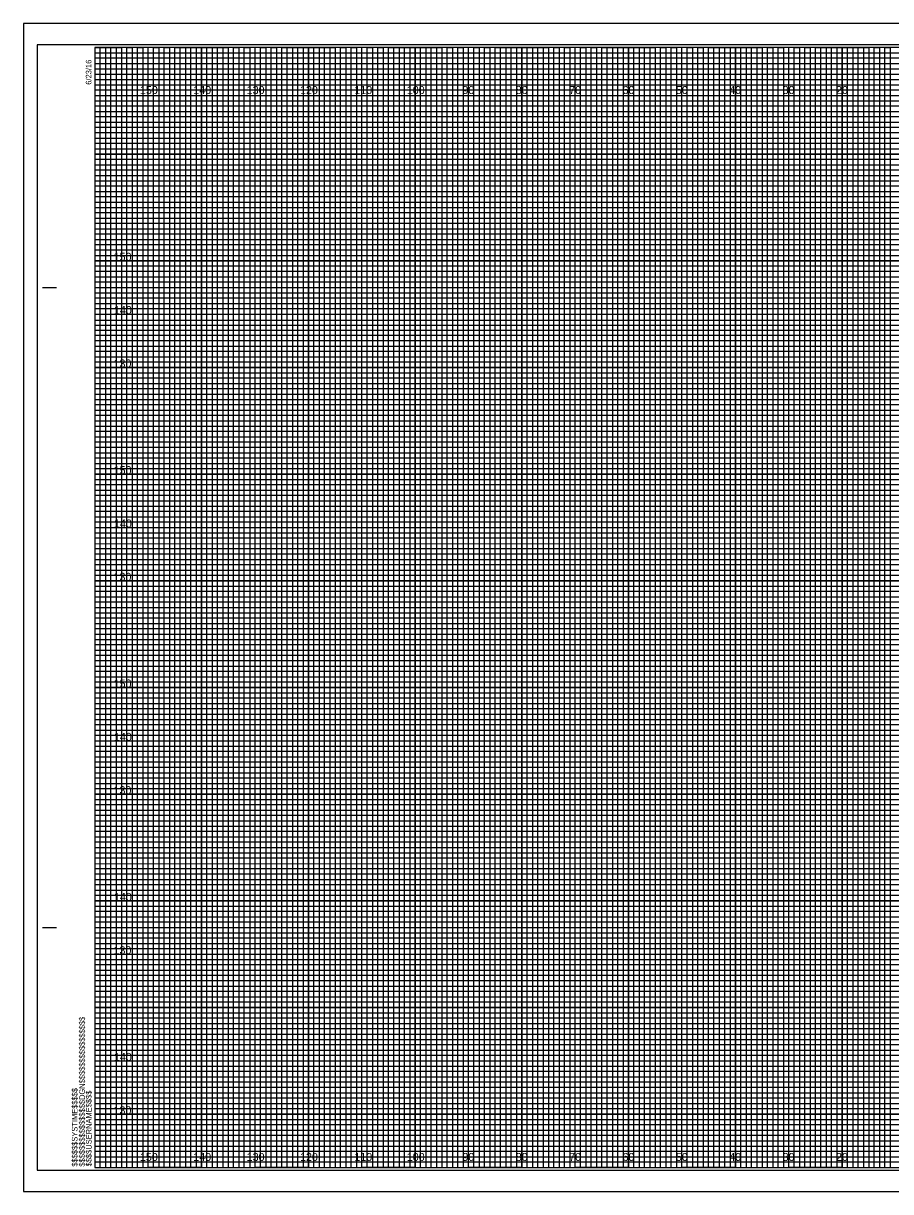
# Model space of a CAD drawing. Extents: x -13 to 323, y -5 to 2634.
# Drawn here: x -13.4 to 149.1, y -4.5 to 214.5 of the extents above; entities that cross this region are included whole.
import ezdxf

# ---------------------------------------------------------------- set-up
doc = ezdxf.new("R2010")
doc.units = 0
for name, color, linetype in [('Exist Cross Section Cell', 7, 'Continuous'), ('Exist XS Center Line Elevation Label', 7, 'Continuous'), ('Exist XS Ground Line', 7, 'Continuous'), ('Prop CMT Pvmt Surface Shoulder', 7, 'Continuous'), ('Prop CMT Pvmt Wedge Surface 3', 7, 'Continuous'), ('Prop CMT Shld Paved Course 1', 7, 'Continuous'), ('Prop CMT Shld Paved Course 2', 7, 'Continuous'), ('Prop CMT Shld Paved Course 3', 7, 'Continuous'), ('Prop CMT Slope Grass', 7, 'Continuous'), ('Prop CMT Subgrade Earthwork', 7, 'Continuous'), ('Scratch_Level_0', 7, 'Continuous')]:
    doc.layers.add(name, color=color, linetype=linetype)

msp = doc.modelspace()

# ---------------------------------------------------------------- linework, layer by layer
at = {"layer": 'Exist XS Center Line Elevation Label'}
for points in [[(0, 210), (5, 210), (5, 0), (15, 0), (15, 210), (25, 210), (25, 0), (35, 0), (35, 210), (45, 210), (45, 0), (55, 0), (55, 210), (65, 210), (65, 0), (75, 0), (75, 210), (85, 210), (85, 0), (95, 0), (95, 210), (105, 210), (105, 0), (115, 0), (115, 210), (125, 210), (125, 0), (135, 0), (135, 210), (145, 210), (145, 0), (155, 0)], [(0, 205), (275, 205)], [(0, 185), (320, 185), (320, 195), (0, 195)], [(0, 165), (320, 165), (320, 175), (0, 175)], [(0, 145), (320, 145), (320, 155), (0, 155)], [(0, 125), (320, 125), (320, 135), (0, 135)], [(0, 105), (320, 105), (320, 115), (0, 115)], [(0, 85), (320, 85), (320, 95), (0, 95)], [(0, 65), (320, 65), (320, 75), (0, 75)], [(0, 45), (320, 45), (320, 55), (0, 55)], [(0, 25), (320, 25), (320, 35), (0, 35)], [(0, 5), (320, 5), (320, 15), (0, 15)]]:
    msp.add_lwpolyline(points, dxfattribs=at)
at = {"layer": 'Exist XS Ground Line'}
for p, q in [((10, 210), (0, 210)), ((10, 0), (10, 210)), ((30, 210), (20, 210)), ((20, 210), (20, 0)), ((30, 0), (30, 210)), ((50, 210), (40, 210)), ((40, 210), (40, 0)), ((50, 0), (50, 210)), ((70, 210), (60, 210)), ((60, 210), (60, 0)), ((70, 0), (70, 210)), ((90, 210), (80, 210)), ((80, 210), (80, 0)), ((90, 0), (90, 210)), ((110, 210), (100, 210)), ((100, 210), (100, 0)), ((110, 0), (110, 210)), ((130, 210), (120, 210)), ((120, 210), (120, 0)), ((130, 0), (130, 210)), ((150, 210), (140, 210)), ((140, 210), (140, 0)), ((20, 0), (10, 0)), ((40, 0), (30, 0)), ((60, 0), (50, 0)), ((80, 0), (70, 0)), ((100, 0), (90, 0)), ((120, 0), (110, 0)), ((140, 0), (130, 0))]:
    msp.add_line(p, q, dxfattribs=at)
for points in [[(0, 200), (320, 200), (320, 190), (0, 190)], [(0, 180), (320, 180), (320, 170), (0, 170)], [(0, 160), (320, 160), (320, 150), (0, 150)], [(0, 140), (320, 140), (320, 130), (0, 130)], [(0, 120), (320, 120), (320, 110), (0, 110)], [(0, 100), (320, 100), (320, 90), (0, 90)], [(0, 80), (320, 80), (320, 70), (0, 70)], [(0, 60), (320, 60), (320, 50), (0, 50)], [(0, 40), (320, 40), (320, 30), (0, 30)], [(0, 20), (320, 20), (320, 10), (0, 10)]]:
    msp.add_lwpolyline(points, dxfattribs=at)
at = {"layer": 'Prop CMT Pvmt Surface Shoulder'}
for points in [[(0, 0), (1, 0), (1, 210), (2, 210), (2, 0)], [(2, 0), (3, 0), (3, 210), (4, 210), (4, 0)], [(5, 0), (6, 0), (6, 210), (7, 210), (7, 0)], [(7, 0), (8, 0), (8, 210), (9, 210), (9, 0)], [(10, 0), (11, 0), (11, 210), (12, 210), (12, 0)], [(12, 0), (13, 0), (13, 210), (14, 210), (14, 0)], [(15, 0), (16, 0), (16, 210), (17, 210), (17, 0)], [(17, 0), (18, 0), (18, 210), (19, 210), (19, 0)], [(20, 0), (21, 0), (21, 210), (22, 210), (22, 0)], [(22, 0), (23, 0), (23, 210), (24, 210), (24, 0)], [(25, 0), (26, 0), (26, 210), (27, 210), (27, 0)], [(27, 0), (28, 0), (28, 210), (29, 210), (29, 0)], [(30, 0), (31, 0), (31, 210), (32, 210), (32, 0)], [(32, 0), (33, 0), (33, 210), (34, 210), (34, 0)], [(35, 0), (36, 0), (36, 210), (37, 210), (37, 0)], [(37, 0), (38, 0), (38, 210), (39, 210), (39, 0)], [(40, 0), (41, 0), (41, 210), (42, 210), (42, 0)], [(42, 0), (43, 0), (43, 210), (44, 210), (44, 0)], [(45, 0), (46, 0), (46, 210), (47, 210), (47, 0)], [(47, 0), (48, 0), (48, 210), (49, 210), (49, 0)], [(50, 0), (51, 0), (51, 210), (52, 210), (52, 0)], [(52, 0), (53, 0), (53, 210), (54, 210), (54, 0)], [(55, 0), (56, 0), (56, 210), (57, 210), (57, 0)], [(57, 0), (58, 0), (58, 210), (59, 210), (59, 0)], [(60, 0), (61, 0), (61, 210), (62, 210), (62, 0)], [(62, 0), (63, 0), (63, 210), (64, 210), (64, 0)], [(65, 0), (66, 0), (66, 210), (67, 210), (67, 0)], [(67, 0), (68, 0), (68, 210), (69, 210), (69, 0)], [(70, 0), (71, 0), (71, 210), (72, 210), (72, 0)], [(72, 0), (73, 0), (73, 210), (74, 210), (74, 0)], [(75, 0), (76, 0), (76, 210), (77, 210), (77, 0)], [(77, 0), (78, 0), (78, 210), (79, 210), (79, 0)], [(80, 0), (81, 0), (81, 210), (82, 210), (82, 0)], [(82, 0), (83, 0), (83, 210), (84, 210), (84, 0)], [(85, 0), (86, 0), (86, 210), (87, 210), (87, 0)], [(87, 0), (88, 0), (88, 210), (89, 210), (89, 0)], [(90, 0), (91, 0), (91, 210), (92, 210), (92, 0)], [(92, 0), (93, 0), (93, 210), (94, 210), (94, 0)], [(95, 0), (96, 0), (96, 210), (97, 210), (97, 0)], [(97, 0), (98, 0), (98, 210), (99, 210), (99, 0)], [(100, 0), (101, 0), (101, 210), (102, 210), (102, 0)], [(102, 0), (103, 0), (103, 210), (104, 210), (104, 0)], [(105, 0), (106, 0), (106, 210), (107, 210), (107, 0)], [(107, 0), (108, 0), (108, 210), (109, 210), (109, 0)], [(110, 0), (111, 0), (111, 210), (112, 210), (112, 0)], [(112, 0), (113, 0), (113, 210), (114, 210), (114, 0)], [(115, 0), (116, 0), (116, 210), (117, 210), (117, 0)], [(117, 0), (118, 0), (118, 210), (119, 210), (119, 0)], [(120, 0), (121, 0), (121, 210), (122, 210), (122, 0)], [(122, 0), (123, 0), (123, 210), (124, 210), (124, 0)], [(125, 0), (126, 0), (126, 210), (127, 210), (127, 0)], [(127, 0), (128, 0), (128, 210), (129, 210), (129, 0)], [(130, 0), (131, 0), (131, 210), (132, 210), (132, 0)], [(132, 0), (133, 0), (133, 210), (134, 210), (134, 0)], [(135, 0), (136, 0), (136, 210), (137, 210), (137, 0)], [(137, 0), (138, 0), (138, 210), (139, 210), (139, 0)], [(140, 0), (141, 0), (141, 210), (142, 210), (142, 0)], [(142, 0), (143, 0), (143, 210), (144, 210), (144, 0)], [(145, 0), (146, 0), (146, 210), (147, 210), (147, 0)], [(147, 0), (148, 0), (148, 210), (149, 210), (149, 0)]]:
    msp.add_lwpolyline(points, dxfattribs=at)
at = {"layer": 'Prop CMT Pvmt Wedge Surface 3'}
for p, q in [((-9.8, 165), (-7.3, 165)), ((-9.7, 165), (-7.2, 165)), ((-9.8, 45), (-7.3, 45)), ((-9.7, 45), (-7.2, 45)), ((0, 0), (0, 0)), ((0, 0), (0, 0)), ((0, 0), (0, 0)), ((0, 0), (0, 0)), ((0, 0), (0, 0)), ((0, 0), (0, 0)), ((0, 0), (0, 0))]:
    msp.add_line(p, q, dxfattribs=at)
msp.add_lwpolyline([(320, 210), (0, 210), (0, 0), (320, 0)], close=True, dxfattribs=at)
at = {"layer": 'Prop CMT Shld Paved Course 1'}
for p, q in [((10, 0), (10, 210)), ((20, 0), (20, 210)), ((30, 0), (30, 210)), ((40, 0), (40, 210)), ((50, 0), (50, 210)), ((60, 0), (60, 210)), ((70, 0), (70, 210)), ((80, 0), (80, 210)), ((90, 0), (90, 210)), ((100, 0), (100, 210)), ((110, 0), (110, 210)), ((120, 0), (120, 210)), ((130, 0), (130, 210)), ((140, 0), (140, 210)), ((0, 200), (320, 200)), ((0, 190), (320, 190)), ((0, 180), (320, 180)), ((0, 170), (320, 170)), ((0, 160), (320, 160)), ((0, 150), (320, 150)), ((0, 140), (320, 140)), ((0, 130), (320, 130)), ((0, 120), (320, 120)), ((0, 110), (320, 110)), ((0, 100), (320, 100)), ((0, 90), (320, 90)), ((0, 80), (320, 80)), ((0, 70), (320, 70)), ((0, 60), (320, 60)), ((0, 50), (320, 50)), ((0, 40), (320, 40)), ((0, 30), (320, 30)), ((0, 20), (320, 20)), ((0, 10), (320, 10))]:
    msp.add_line(p, q, dxfattribs=at)
at = {"layer": 'Prop CMT Shld Paved Course 2'}
for p, q in [((323.3, 214.5), (-13.4, 214.5)), ((-13.4, 214.5), (-13.4, -4.5)), ((-13.4, -4.5), (323.3, -4.5))]:
    msp.add_line(p, q, dxfattribs=at)
at = {"layer": 'Prop CMT Slope Grass'}
msp.add_lwpolyline([(-10.8, -0.5), (322.4, -0.5), (322.4, 210.5), (-10.8, 210.5)], close=True, dxfattribs=at)
at = {"layer": 'Prop CMT Subgrade Earthwork'}
msp.add_lwpolyline([(-13.4, -4.5), (323.3, -4.5), (323.3, 214.5), (-13.4, 214.5)], close=True, dxfattribs=at)
at = {"layer": 'Scratch_Level_0'}
for p, q in [((0, 209), (260, 209)), ((260, 207.98), (0, 207.98)), ((0, 207.98), (0, 207)), ((0, 207), (260, 207)), ((260, 205.89), (0, 205.89)), ((0, 205.89), (0, 204)), ((0, 204), (320, 204))]:
    msp.add_line(p, q, dxfattribs=at)
for points in [[(0, 203), (270, 203), (320, 203), (320, 202), (0, 202)], [(0, 201), (320, 201), (320, 199), (0, 199)], [(0, 198), (320, 198), (320, 197), (0, 196.98)], [(0, 196), (320, 196), (320, 194), (0, 194)], [(0, 193), (320, 193), (320, 192), (0, 192)], [(0, 191), (320, 191), (320, 189), (0, 189)], [(0, 188), (320, 188), (320, 187), (0, 187)], [(0, 186), (320, 186), (320, 184), (0, 184)], [(0, 183), (320, 183), (320, 182), (0, 182)], [(0, 181), (320, 181), (320, 179), (0, 179)], [(0, 178), (320, 178), (320, 177), (0, 177)], [(0, 176), (320, 176), (320, 173.95), (320, 173), (320, 172), (0, 172)], [(0, 174), (320, 174), (320, 173), (0, 173)], [(0, 171), (320, 171), (320, 169), (0, 169.03)], [(0, 169.03), (320, 169), (320, 168), (0, 168)], [(0, 167), (320, 167), (320, 166), (0, 166)], [(0, 164), (320, 164), (320, 163), (0, 163)], [(0, 162), (320, 162), (320, 161), (0, 161)], [(-0.07, 158.89), (320, 158.89), (320, 157.88), (-0.07, 157.88)], [(0, 157), (320, 157), (320, 156), (0, 156)], [(0, 154), (320, 154), (320, 153), (0, 153)], [(0, 152), (320, 152), (320, 151), (0, 151)], [(0, 149), (320, 149), (320, 148), (0, 148)], [(0, 147), (320, 147), (320, 146), (0, 146)], [(0, 144), (320, 144), (320, 143), (0, 143)], [(0, 142), (320, 142), (320, 141), (0, 141)], [(0, 139), (320, 139), (319.99, 137.98), (0, 138)], [(0, 137), (320, 137), (320, 136), (0, 136)], [(0, 134), (320, 134), (320, 133), (0, 133)], [(0, 132), (320, 132), (320, 131), (0, 131)], [(0, 129), (320, 129), (320, 128), (0, 128)], [(0, 127), (320, 127), (320, 126), (0, 126)], [(0, 124), (320, 124), (320, 123), (0, 123)], [(0, 122), (320, 122), (320, 121), (0, 121)], [(0, 119), (320, 119), (320, 118), (0, 118)], [(0, 116.99), (320.07, 116.91), (320, 116), (0, 116)], [(0, 114), (320, 114), (320, 113), (0, 113)], [(0, 112), (320, 112), (320, 111), (0, 111)], [(0, 109), (320, 109), (320, 108), (0, 108)], [(0, 107), (320, 107), (320, 106), (0, 106)], [(0, 104), (320, 104), (320, 103), (0, 103)], [(0, 102), (320, 102), (320, 101), (0, 101)], [(0, 99), (320, 99), (320, 98), (0, 98)], [(0, 97), (320, 97), (320, 96), (0, 96)], [(0, 94), (320, 94), (320, 93), (0, 93)], [(0, 92), (320, 92), (320, 91), (0, 91)], [(0, 89), (320, 89), (320, 88), (0, 88)], [(0, 87), (320, 87), (320, 86), (0, 86)], [(0, 84), (320, 84), (320, 83), (0, 83)], [(0, 82), (320, 82), (320, 81), (0, 81)], [(0, 79), (320, 79), (319.99, 77.98), (0, 78)], [(0, 77), (320, 77), (320, 76), (0, 76)], [(0, 74), (320, 74), (320, 73), (0, 73)], [(0, 72), (320, 72), (320, 71), (0, 71)], [(0, 69), (320, 69), (320, 68), (0, 68)], [(0, 67), (320, 67), (320, 66), (0, 66)], [(0, 64), (320, 64), (320, 63), (0, 63)], [(0, 62), (320, 62), (320, 61), (0, 61)], [(0, 59), (320, 59), (320, 58), (0, 58)], [(0, 56.99), (320.07, 56.91), (320, 56), (0, 56)], [(0, 54), (320, 54), (320, 53), (0, 53)], [(0, 52), (320, 52), (320, 51), (0, 51)], [(0, 49), (320, 49), (320, 48), (0, 48)], [(0, 47), (320, 47), (320, 46), (0, 46)], [(0, 44), (320, 44), (320, 43), (0, 43)], [(0, 42), (320, 42), (320, 41), (0, 41)], [(0, 39), (320, 39), (320, 38), (0, 38)], [(0, 37), (320, 37), (320, 36), (0, 36)], [(0, 34), (320, 34), (320, 33), (0, 33)], [(0, 32), (320, 32), (320, 31), (0, 31)], [(0, 29), (320, 29), (320, 28), (0, 28)], [(0, 27), (320, 27), (320, 26), (0, 26)], [(0, 24), (320, 24), (320, 23), (0, 23)], [(0, 22), (320, 22), (320, 21), (0, 21)], [(0, 19), (320, 19), (320, 18), (0, 18)], [(0, 17), (320, 17), (320, 16), (0, 16)], [(0, 14), (320, 14), (320, 13), (0, 13)], [(0, 12), (320, 12), (320, 11), (0, 11)], [(0, 9), (320, 9), (320, 8), (0, 8)], [(0, 7), (320, 7), (320, 6), (0, 6)], [(0, 4), (320, 4), (320, 3), (0, 3)], [(0, 2), (320, 2), (320, 1), (0, 1)]]:
    msp.add_lwpolyline(points, dxfattribs=at)

# ---------------------------------------------------------------- texts
at = {"layer": 'Exist Cross Section Cell'}
for s, p in [('150', (8.44, 201.25)), ('140', (18.44, 201.25)), ('130', (28.44, 201.25)), ('120', (38.44, 201.25)), ('110', (48.62, 201.25)), ('100', (58.44, 201.25)), ('90', (68.86, 201.25)), ('80', (78.86, 201.25)), ('70', (88.86, 201.25)), ('60', (98.86, 201.25)), ('50', (108.86, 201.25)), ('40', (118.86, 201.25)), ('30', (128.86, 201.25)), ('20', (138.86, 201.25)), ('150', (8.44, 1.25)), ('140', (18.44, 1.25)), ('130', (28.44, 1.25)), ('120', (38.44, 1.25)), ('110', (48.62, 1.25)), ('100', (58.44, 1.25)), ('90', (68.86, 1.25)), ('80', (78.86, 1.25)), ('70', (88.86, 1.25)), ('60', (98.86, 1.25)), ('50', (108.86, 1.25)), ('40', (118.86, 1.25)), ('30', (128.86, 1.25)), ('20', (138.86, 1.25))]:
    msp.add_text(s, height=1.5, dxfattribs=at).set_placement(p)
at = {"layer": 'Prop CMT Pvmt Wedge Surface 3'}
for s, p in [('6/23/16', (-0.65, 203)), ('$$$$$$$$$$$$$$$$DGN$$$$$$$$$$$$$$$$', (-1.88, 0.18)), ('$$$$$$SYSTIME$$$$$', (-3.26, 0.18)), ('$$$$USERNAME$$$$', (-0.62, 0.23))]:
    msp.add_text(s, height=1.05, rotation=90, dxfattribs=at).set_placement(p)
at = {"layer": 'Prop CMT Shld Paved Course 3'}
for s, p in [('150', (3.52, 170)), ('140', (3.57, 160)), ('130', (3.49, 150)), ('150', (3.52, 130)), ('140', (3.57, 120)), ('130', (3.49, 110)), ('150', (3.52, 90)), ('140', (3.57, 80)), ('130', (3.49, 70)), ('140', (3.57, 50)), ('130', (3.49, 40)), ('140', (3.57, 20)), ('130', (3.49, 10))]:
    msp.add_text(s, height=1.5, dxfattribs=at).set_placement(p)

doc.saveas('drawing.dxf')
